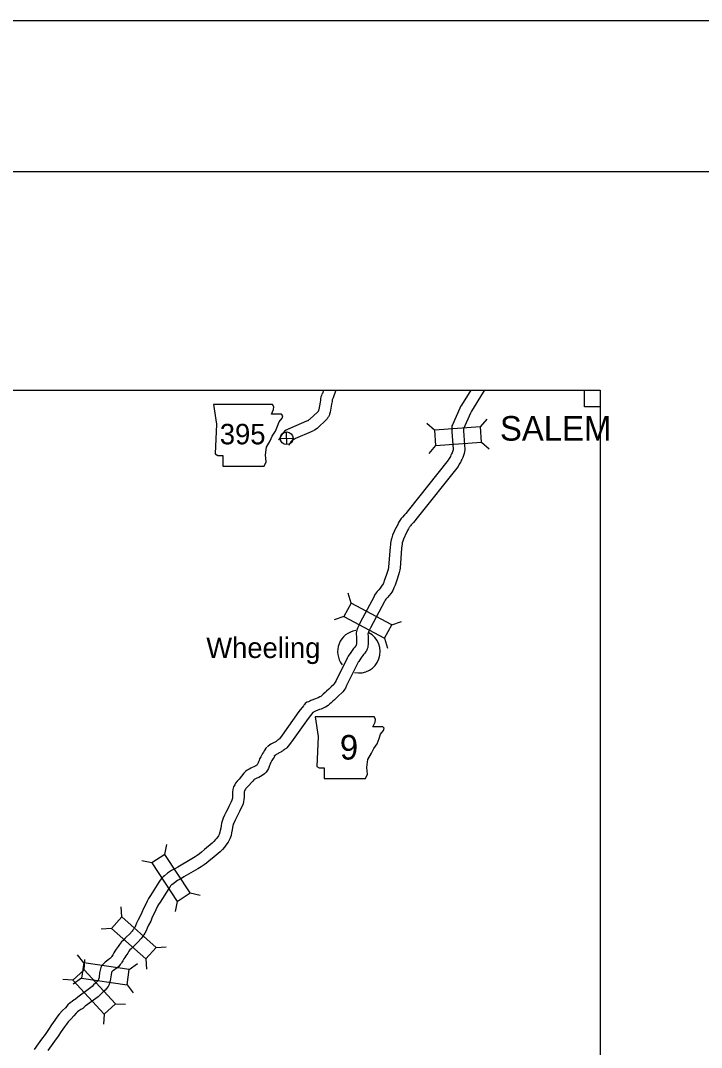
# Model space of a CAD drawing. Extents: x 1377389 to 1380723, y 1168351 to 1170484.
# Drawn here: x 1378129.6 to 1378305.3, y 1170219.2 to 1170484.1 of the extents above; entities that cross this region are included whole.
import ezdxf

# ---------------------------------------------------------------- set-up
doc = ezdxf.new("R2010")
doc.units = 0
doc.layers.add('B_Fill', color=7, linetype='Continuous')
doc.layers.add('B_Text', color=7, linetype='Continuous')

msp = doc.modelspace()

# ---------------------------------------------------------------- linework, layer by layer
msp.add_line((1377513.42, 1170445.16), (1380675.22, 1170445.16))
at = {"layer": 'B_Fill'}
for p, q in [((1378275.14, 1170384.45), (1378275.07, 1170388.77)), ((1378275.07, 1170388.77), (1378279.16, 1170388.77)), ((1378279.16, 1170388.77), (1378279.16, 1170384.42)), ((1378279.16, 1170384.42), (1378275.14, 1170384.45)), ((1378236.4, 1170378.4), (1378234.4, 1170380.12)), ((1378248.25, 1170379.3), (1378249.97, 1170381.3)), ((1378198.32, 1170374.72), (1378198.24, 1170377.98)), ((1378196.65, 1170376.31), (1378199.91, 1170376.39)), ((1378236.7, 1170374.45), (1378234.98, 1170372.45)), ((1378248.55, 1170375.35), (1378250.55, 1170373.63)), ((1378214.89, 1170333.82), (1378214.12, 1170336.35)), ((1378213.04, 1170330.33), (1378210.51, 1170329.55)), ((1378225.39, 1170328.26), (1378227.91, 1170329.04)), ((1378223.54, 1170324.76), (1378224.31, 1170322.24)), ((1378166.84, 1170268.99), (1378167.38, 1170271.57)), ((1378163.53, 1170266.82), (1378160.95, 1170267.35)), ((1378173.36, 1170259.05), (1378175.94, 1170258.51)), ((1378155.72, 1170252.87), (1378155.56, 1170255.51)), ((1378170.04, 1170256.88), (1378169.51, 1170254.3)), ((1378153.09, 1170249.91), (1378150.45, 1170249.75)), ((1378164.6, 1170244.98), (1378167.23, 1170245.14)), ((1378145.91, 1170240.99), (1378144.33, 1170243.11)), ((1378146.08, 1170239.26), (1378146.2, 1170241.89)), ((1378161.97, 1170242.02), (1378162.12, 1170239.38)), ((1378157.67, 1170239.29), (1378159.78, 1170240.87)), ((1378143.15, 1170236.59), (1378140.51, 1170236.71)), ((1378145.34, 1170237.08), (1378143.23, 1170235.49)), ((1378157.1, 1170235.37), (1378158.68, 1170233.26)), ((1378154.09, 1170230.48), (1378156.72, 1170230.36)), ((1378151.16, 1170227.81), (1378151.04, 1170225.17))]:
    msp.add_line(p, q, dxfattribs=at)
for points in [[(1378207.79, 1170388.77), (1378207.48, 1170387.93), (1378207.36, 1170387.68), (1378207.23, 1170387.37), (1378207.1, 1170387.02), (1378207.03, 1170386.55), (1378206.99, 1170386.17), (1378206.92, 1170385.65), (1378206.59, 1170383.78), (1378206.52, 1170383.56), (1378206.48, 1170383.45), (1378206.46, 1170383.43), (1378206.43, 1170383.37), (1378206.36, 1170383.28), (1378206.12, 1170383), (1378204.36, 1170381.38), (1378204.16, 1170381.17), (1378204.03, 1170381.08), (1378203.72, 1170380.87)], [(1378210.98, 1170388.77), (1378210.26, 1170386.79), (1378210.1, 1170386.45), (1378210.02, 1170386.27), (1378210, 1170386.17), (1378209.97, 1170385.83), (1378209.88, 1170385.18), (1378209.51, 1170383.06), (1378209.34, 1170382.53), (1378209.29, 1170382.4), (1378209.23, 1170382.22), (1378209.04, 1170381.88), (1378208.9, 1170381.67), (1378208.69, 1170381.38), (1378208.27, 1170380.9), (1378206.48, 1170379.25), (1378206.11, 1170378.86), (1378205.71, 1170378.59), (1378205.41, 1170378.39)], [(1378245.75, 1170388.77), (1378243.37, 1170384.89), (1378243.15, 1170384.51), (1378242.96, 1170384.08), (1378241.01, 1170379.83), (1378240.92, 1170379.57), (1378240.89, 1170379.37), (1378240.84, 1170379.11), (1378240.84, 1170378.62), (1378240.86, 1170378.49), (1378240.85, 1170378.34), (1378240.88, 1170378.02), (1378241.22, 1170373.54), (1378241.2, 1170373.35), (1378241.15, 1170373.11), (1378241.07, 1170372.82), (1378241, 1170372.62), (1378240.83, 1170372.3), (1378240.64, 1170371.95), (1378240.51, 1170371.67), (1378240.34, 1170371.37), (1378240.2, 1170371.12), (1378240.05, 1170370.85), (1378239.93, 1170370.66), (1378229.59, 1170357.71), (1378228.98, 1170356.93), (1378228.7, 1170356.6), (1378228.15, 1170356), (1378227.85, 1170355.63), (1378227.65, 1170355.38), (1378227.46, 1170355.1), (1378227.3, 1170354.85), (1378227.06, 1170354.42), (1378226.91, 1170354.14), (1378226.76, 1170353.87), (1378226.48, 1170353.28)], [(1378249.33, 1170388.77), (1378249.14, 1170388.52), (1378248.96, 1170388.26), (1378245.95, 1170383.35), (1378245.83, 1170383.15), (1378245.7, 1170382.85), (1378243.85, 1170378.82), (1378243.88, 1170378.66), (1378243.86, 1170378.4), (1378243.87, 1170378.27), (1378244.24, 1170373.46), (1378244.16, 1170372.87), (1378244.08, 1170372.44), (1378243.93, 1170371.9), (1378243.74, 1170371.4), (1378243.49, 1170370.9), (1378243.31, 1170370.57), (1378243.17, 1170370.29), (1378242.96, 1170369.91), (1378242.81, 1170369.65), (1378242.48, 1170369.05), (1378231.94, 1170355.85), (1378231.31, 1170355.05), (1378230.96, 1170354.62), (1378230.41, 1170354.03), (1378230.2, 1170353.77), (1378230.07, 1170353.61), (1378229.95, 1170353.43), (1378229.87, 1170353.3), (1378229.69, 1170352.98), (1378229.56, 1170352.74), (1378229.45, 1170352.52), (1378229.18, 1170351.98)], [(1378203.89, 1170380.97), (1378203.64, 1170380.84), (1378203.36, 1170380.72), (1378199.3, 1170378.98), (1378198.94, 1170378.8), (1378198.83, 1170378.75), (1378198.48, 1170378.62), (1378198.14, 1170378.42), (1378197.75, 1170378.15), (1378197.57, 1170377.94), (1378197.43, 1170377.81), (1378197.24, 1170377.58), (1378196.73, 1170376.92), (1378196.18, 1170375.84)], [(1378205.25, 1170378.3), (1378204.93, 1170378.14), (1378204.57, 1170377.97), (1378200.56, 1170376.26), (1378200.26, 1170376.1), (1378199.99, 1170375.98), (1378199.78, 1170375.9), (1378199.62, 1170375.75), (1378199.57, 1170375.69), (1378199.27, 1170375.3), (1378198.86, 1170374.49)], [(1378226.47, 1170353.26), (1378225.59, 1170351.36), (1378225.39, 1170350.68), (1378225.21, 1170350.15), (1378225.11, 1170349.7), (1378225.04, 1170349.29), (1378225.03, 1170348.88), (1378224.94, 1170348.3), (1378224.52, 1170343.1), (1378224.5, 1170342.81), (1378224.48, 1170342.7), (1378224.42, 1170342.49), (1378224.04, 1170341.22), (1378223.46, 1170339.58), (1378223.3, 1170339.23), (1378223.15, 1170338.82), (1378223.06, 1170338.56), (1378222.95, 1170338.42), (1378222.77, 1170338.16), (1378222.37, 1170337.68), (1378222.02, 1170337.25), (1378221.59, 1170336.83), (1378221.38, 1170336.49), (1378220.91, 1170335.86), (1378220.87, 1170335.62), (1378220.83, 1170335.55), (1378217.27, 1170328.83), (1378216.86, 1170328.08), (1378216.7, 1170327.72), (1378216.54, 1170327.32), (1378216.47, 1170327.08), (1378216.39, 1170326.84), (1378216.3, 1170326.51), (1378216.24, 1170326.15), (1378216.22, 1170325.77), (1378216.26, 1170325.16), (1378216.28, 1170323.39), (1378216.25, 1170323.21), (1378216.22, 1170323.03), (1378216.22, 1170323.01), (1378216.21, 1170323), (1378216.17, 1170322.93), (1378216.02, 1170322.71), (1378215.82, 1170322.47), (1378215.55, 1170322.14), (1378214.98, 1170321.36), (1378214.63, 1170320.86), (1378214.34, 1170320.4), (1378214.14, 1170320.1), (1378213.88, 1170319.58), (1378211.04, 1170313.86), (1378210.81, 1170313.4), (1378210.64, 1170313.13), (1378210.49, 1170312.88), (1378210.44, 1170312.81), (1378210.44, 1170312.81), (1378209.73, 1170312.21), (1378209.16, 1170311.63), (1378208.58, 1170311.1), (1378208.19, 1170310.75), (1378207.7, 1170310.32), (1378207.38, 1170309.99), (1378207.15, 1170309.79), (1378207.07, 1170309.74), (1378206.86, 1170309.68), (1378206.37, 1170309.4), (1378206.16, 1170309.32), (1378205.68, 1170309.16), (1378204.53, 1170308.67), (1378204.25, 1170308.54), (1378203.87, 1170308.39), (1378203.51, 1170308.23), (1378203.08, 1170307.92), (1378202.85, 1170307.67), (1378202.71, 1170307.52), (1378202.59, 1170307.35), (1378201.43, 1170305.83), (1378197.09, 1170299.78)], [(1378229.19, 1170352), (1378228.41, 1170350.31), (1378228.26, 1170349.78), (1378228.1, 1170349.34), (1378228.05, 1170349.12), (1378228.03, 1170348.99), (1378228.02, 1170348.61), (1378227.92, 1170347.96), (1378227.51, 1170342.84), (1378227.47, 1170342.42), (1378227.41, 1170342.07), (1378227.31, 1170341.69), (1378226.9, 1170340.29), (1378226.25, 1170338.47), (1378226.08, 1170338.08), (1378225.96, 1170337.79), (1378225.86, 1170337.51), (1378225.7, 1170337.09), (1378225.38, 1170336.65), (1378225.15, 1170336.33), (1378224.69, 1170335.78), (1378224.25, 1170335.23), (1378223.95, 1170334.94), (1378223.86, 1170334.8), (1378223.67, 1170334.55), (1378223.52, 1170334.22), (1378219.91, 1170327.41), (1378219.55, 1170326.74), (1378219.46, 1170326.55), (1378219.38, 1170326.35), (1378219.33, 1170326.18), (1378219.26, 1170325.95), (1378219.23, 1170325.86), (1378219.23, 1170325.84), (1378219.22, 1170325.79), (1378219.26, 1170325.28), (1378219.28, 1170323.2), (1378219.22, 1170322.72), (1378219.19, 1170322.56), (1378219.17, 1170322.4), (1378219.08, 1170322.05), (1378218.97, 1170321.81), (1378218.83, 1170321.52), (1378218.68, 1170321.3), (1378218.43, 1170320.92), (1378218.13, 1170320.55), (1378217.92, 1170320.3), (1378217.42, 1170319.62), (1378217.13, 1170319.21), (1378216.86, 1170318.77), (1378216.74, 1170318.6), (1378216.57, 1170318.24), (1378213.72, 1170312.53), (1378213.42, 1170311.92), (1378213.19, 1170311.55), (1378213, 1170311.24), (1378212.79, 1170310.94), (1378212.52, 1170310.65), (1378211.77, 1170310.01), (1378211.25, 1170309.48), (1378210.59, 1170308.87), (1378210.18, 1170308.51), (1378209.77, 1170308.14), (1378209.44, 1170307.81), (1378208.97, 1170307.4), (1378208.33, 1170306.98), (1378208.03, 1170306.89), (1378207.67, 1170306.69), (1378207.19, 1170306.5), (1378206.74, 1170306.35), (1378205.73, 1170305.92), (1378205.41, 1170305.77), (1378205.06, 1170305.64), (1378205.03, 1170305.59), (1378203.84, 1170304.04), (1378199.53, 1170298.04)], [(1378197.09, 1170299.79), (1378196.39, 1170298.81), (1378196.31, 1170298.73), (1378196.28, 1170298.71), (1378196.12, 1170298.59), (1378195.95, 1170298.44), (1378195.84, 1170298.36), (1378195.7, 1170298.26), (1378195.53, 1170298.14), (1378195.4, 1170298.06), (1378195.28, 1170297.99), (1378195.05, 1170297.87), (1378194.7, 1170297.7), (1378194.52, 1170297.58), (1378194.39, 1170297.52), (1378194.18, 1170297.41), (1378193.48, 1170296.94), (1378193.38, 1170296.83), (1378193.26, 1170296.75)], [(1378199.52, 1170298.03), (1378198.7, 1170296.89), (1378198.36, 1170296.53), (1378198.15, 1170296.36), (1378198, 1170296.25), (1378197.84, 1170296.12), (1378197.63, 1170295.95), (1378197.4, 1170295.78), (1378197.18, 1170295.64), (1378196.98, 1170295.51), (1378196.74, 1170295.37), (1378196.38, 1170295.18), (1378196.2, 1170295.09), (1378196.01, 1170294.96), (1378195.72, 1170294.83), (1378195.62, 1170294.77), (1378195.45, 1170294.65), (1378195.29, 1170294.51), (1378195, 1170294.31)], [(1378193.15, 1170296.67), (1378192.93, 1170296.44), (1378192.66, 1170295.99), (1378192.5, 1170295.71), (1378192.27, 1170295.36), (1378192.05, 1170295.02), (1378191.88, 1170294.71), (1378191.58, 1170294.2), (1378191.3, 1170293.67), (1378191.14, 1170293.21), (1378191.05, 1170292.91), (1378190.93, 1170292.6), (1378190.87, 1170292.47), (1378190.77, 1170292.29), (1378190.65, 1170292.11), (1378190.54, 1170291.99), (1378190.34, 1170291.85), (1378190.12, 1170291.72), (1378189.82, 1170291.58), (1378189.39, 1170291.39), (1378189.01, 1170291.23), (1378188.57, 1170291.03), (1378188.1, 1170290.77), (1378187.67, 1170290.37), (1378187.26, 1170289.92), (1378185.98, 1170288.42), (1378185.49, 1170287.92), (1378185.11, 1170287.41), (1378184.87, 1170286.97), (1378184.57, 1170286.4), (1378184.39, 1170285.72), (1378184.32, 1170285.09), (1378184.3, 1170284.68), (1378184.3, 1170284.21), (1378184.3, 1170283.89), (1378184.28, 1170283.54), (1378184.23, 1170283.29), (1378184.15, 1170282.95), (1378184, 1170282.53), (1378183.73, 1170282.06), (1378183.38, 1170281.32), (1378183.03, 1170280.58), (1378182.61, 1170279.79), (1378182.26, 1170279.13), (1378181.91, 1170278.35), (1378181.68, 1170277.85), (1378181.46, 1170277.08), (1378181.34, 1170276.37), (1378181.27, 1170275.81), (1378181.15, 1170275.19), (1378181.04, 1170274.72), (1378180.86, 1170274.17), (1378180.66, 1170273.77), (1378180.23, 1170273.2), (1378179.95, 1170272.84), (1378179.48, 1170272.32), (1378179.07, 1170271.88), (1378177.09, 1170270.27), (1378176.34, 1170269.61), (1378175.76, 1170269.15), (1378175.22, 1170268.74), (1378174.65, 1170268.35), (1378173.85, 1170267.9), (1378170.19, 1170265.73), (1378169.63, 1170265.38), (1378169.22, 1170265.16), (1378168.57, 1170264.81), (1378167.53, 1170264.13), (1378166.76, 1170263.5), (1378166.43, 1170263.23), (1378166.02, 1170262.81), (1378165.67, 1170262.34), (1378165.33, 1170261.85), (1378163.15, 1170258.37), (1378162.65, 1170257.65), (1378162.29, 1170256.96), (1378161.82, 1170256.01), (1378161.36, 1170255.05), (1378160.88, 1170254.01), (1378160.48, 1170253.1), (1378159.98, 1170252.12), (1378159.56, 1170251.23), (1378159.28, 1170250.58), (1378159.08, 1170250.17), (1378158.95, 1170249.96), (1378158.86, 1170249.84), (1378158.71, 1170249.63), (1378158.58, 1170249.43), (1378158.4, 1170249.2), (1378157.72, 1170248.44), (1378156.96, 1170247.7), (1378156.53, 1170247.29), (1378156.08, 1170246.83), (1378155.64, 1170246.41), (1378155.14, 1170245.77), (1378154.77, 1170245.22), (1378154.3, 1170244.52), (1378153.97, 1170244.04), (1378153.7, 1170243.58), (1378153.43, 1170243.09), (1378153.15, 1170242.66)], [(1378195.34, 1170294.62), (1378195.24, 1170294.46), (1378195.04, 1170294.12), (1378194.79, 1170293.74), (1378194.62, 1170293.48), (1378194.47, 1170293.21), (1378194.2, 1170292.74), (1378194.06, 1170292.49), (1378193.99, 1170292.28), (1378193.88, 1170291.93), (1378193.7, 1170291.45), (1378193.55, 1170291.12), (1378193.31, 1170290.69), (1378192.99, 1170290.23), (1378192.56, 1170289.76), (1378191.97, 1170289.32), (1378191.5, 1170289.06), (1378191.07, 1170288.85), (1378190.56, 1170288.63), (1378190.22, 1170288.49), (1378189.93, 1170288.35), (1378189.88, 1170288.32), (1378189.8, 1170288.25), (1378189.51, 1170287.93), (1378188.19, 1170286.39), (1378187.77, 1170285.96), (1378187.65, 1170285.79), (1378187.52, 1170285.56), (1378187.38, 1170285.3), (1378187.35, 1170285.18), (1378187.32, 1170284.84), (1378187.3, 1170284.59), (1378187.3, 1170284.21), (1378187.3, 1170283.8), (1378187.26, 1170283.19), (1378187.17, 1170282.65), (1378187.02, 1170282.08), (1378186.74, 1170281.27), (1378186.4, 1170280.68), (1378186.1, 1170280.04), (1378185.71, 1170279.22), (1378185.26, 1170278.38), (1378184.96, 1170277.81), (1378184.63, 1170277.1), (1378184.5, 1170276.82), (1378184.39, 1170276.41), (1378184.31, 1170275.94), (1378184.24, 1170275.35), (1378184.08, 1170274.56), (1378183.94, 1170273.92), (1378183.64, 1170273.02), (1378183.21, 1170272.18), (1378182.61, 1170271.38), (1378182.24, 1170270.9), (1378181.68, 1170270.29), (1378181.12, 1170269.69), (1378179.03, 1170267.98), (1378178.26, 1170267.31), (1378177.59, 1170266.77), (1378176.97, 1170266.31), (1378176.24, 1170265.8), (1378175.35, 1170265.3), (1378171.76, 1170263.18), (1378171.14, 1170262.78), (1378170.63, 1170262.51), (1378170.11, 1170262.23), (1378169.3, 1170261.71), (1378168.65, 1170261.17), (1378168.47, 1170261.03), (1378168.31, 1170260.86), (1378168.11, 1170260.59), (1378167.85, 1170260.21), (1378165.65, 1170256.71), (1378165.22, 1170256.09), (1378164.97, 1170255.61), (1378164.52, 1170254.7), (1378164.07, 1170253.77), (1378163.61, 1170252.78), (1378163.2, 1170251.82), (1378162.67, 1170250.79), (1378162.3, 1170250.01), (1378162.01, 1170249.31), (1378161.7, 1170248.72), (1378161.44, 1170248.28), (1378161.29, 1170248.08), (1378161.18, 1170247.92), (1378160.99, 1170247.65), (1378160.7, 1170247.28), (1378159.89, 1170246.37), (1378159.05, 1170245.54), (1378158.64, 1170245.15), (1378158.18, 1170244.68), (1378157.86, 1170244.38), (1378157.57, 1170244.01), (1378157.27, 1170243.55), (1378156.77, 1170242.82), (1378156.51, 1170242.44), (1378156.31, 1170242.1), (1378156, 1170241.55), (1378155.7, 1170241.06)], [(1378153.21, 1170242.74), (1378152.99, 1170242.44), (1378152.83, 1170242.25), (1378152.58, 1170242.04), (1378152.17, 1170241.73), (1378151.76, 1170241.43), (1378151.45, 1170241.17), (1378151.07, 1170240.84), (1378150.59, 1170240.36), (1378150.36, 1170239.86), (1378150.24, 1170239.5), (1378150.15, 1170239.13), (1378150.02, 1170238.43), (1378149.87, 1170237.39), (1378149.8, 1170237.03), (1378149.73, 1170236.75), (1378149.68, 1170236.6), (1378149.62, 1170236.47), (1378149.57, 1170236.4), (1378149.34, 1170236.17), (1378148.93, 1170235.79), (1378148.47, 1170235.36), (1378148.06, 1170234.93), (1378147.73, 1170234.63), (1378144.41, 1170232.2), (1378143.83, 1170231.67), (1378143.48, 1170231.45), (1378142.93, 1170231.06), (1378142.44, 1170230.69), (1378141.86, 1170230.16), (1378141.2, 1170229.45), (1378140.48, 1170228.7), (1378139.6, 1170227.78), (1378139.03, 1170227.04), (1378138.49, 1170226.27), (1378137.61, 1170225.01), (1378136.81, 1170223.81), (1378135.94, 1170222.57), (1378135.07, 1170221.38), (1378134.21, 1170220.13), (1378133.13, 1170218.64)], [(1378155.64, 1170240.98), (1378155.34, 1170240.56), (1378154.94, 1170240.11), (1378154.45, 1170239.69), (1378153.96, 1170239.33), (1378153.62, 1170239.08), (1378153.39, 1170238.88), (1378153.12, 1170238.65), (1378153.12, 1170238.65), (1378153.09, 1170238.51), (1378152.99, 1170237.95), (1378152.83, 1170236.87), (1378152.73, 1170236.37), (1378152.61, 1170235.9), (1378152.46, 1170235.47), (1378152.2, 1170234.91), (1378151.84, 1170234.44), (1378151.43, 1170234.02), (1378150.97, 1170233.59), (1378150.59, 1170233.24), (1378150.16, 1170232.79), (1378149.63, 1170232.3), (1378146.31, 1170229.87), (1378145.66, 1170229.28), (1378145.16, 1170228.97), (1378144.7, 1170228.63), (1378144.34, 1170228.37), (1378143.97, 1170228.03), (1378143.39, 1170227.4), (1378142.65, 1170226.62), (1378141.88, 1170225.82), (1378141.44, 1170225.25), (1378140.94, 1170224.55), (1378140.09, 1170223.32), (1378139.29, 1170222.12), (1378138.37, 1170220.81), (1378137.51, 1170219.64), (1378136.66, 1170218.4)]]:
    msp.add_lwpolyline(points, dxfattribs=at)
for points in [[(1378179.43, 1170385.08), (1378180.19, 1170380), (1378179.85, 1170372.31), (1378180.53, 1170371.88), (1378181.8, 1170371.88), (1378181.8, 1170369.18), (1378192.46, 1170369.18), (1378192.96, 1170370.28), (1378192.79, 1170372.05), (1378193.05, 1170374.08), (1378193.98, 1170375.69), (1378194.57, 1170376.88), (1378195.42, 1170378.14), (1378195.92, 1170379.5), (1378196.35, 1170380.6), (1378197.11, 1170381.53), (1378197.28, 1170382.12), (1378196.94, 1170382.54), (1378194.32, 1170382.54), (1378194.91, 1170383.73), (1378194.99, 1170384.49), (1378194.64, 1170385.07)], [(1378236.7, 1170374.45), (1378248.55, 1170375.35), (1378248.25, 1170379.3), (1378236.4, 1170378.4)], [(1378225.39, 1170328.26), (1378214.89, 1170333.82), (1378213.04, 1170330.33), (1378223.54, 1170324.76)], [(1378205.6, 1170304.49), (1378206.36, 1170299.41), (1378206.03, 1170291.71), (1378206.7, 1170291.29), (1378207.97, 1170291.29), (1378207.97, 1170288.58), (1378218.63, 1170288.58), (1378219.14, 1170289.68), (1378218.97, 1170291.46), (1378219.22, 1170293.49), (1378220.15, 1170295.1), (1378220.74, 1170296.28), (1378221.59, 1170297.55), (1378222.1, 1170298.9), (1378222.52, 1170300), (1378223.28, 1170300.93), (1378223.45, 1170301.53), (1378223.11, 1170301.95), (1378220.49, 1170301.95), (1378221.08, 1170303.13), (1378221.17, 1170303.89), (1378220.82, 1170304.48)], [(1378173.36, 1170259.05), (1378166.84, 1170268.99), (1378163.53, 1170266.82), (1378170.04, 1170256.88)], [(1378164.6, 1170244.98), (1378155.72, 1170252.87), (1378153.09, 1170249.91), (1378161.97, 1170242.02)], [(1378143.15, 1170236.59), (1378151.16, 1170227.81), (1378154.09, 1170230.48), (1378146.08, 1170239.26)], [(1378145.34, 1170237.08), (1378157.1, 1170235.37), (1378157.67, 1170239.29), (1378145.91, 1170240.99)]]:
    msp.add_lwpolyline(points, close=True, dxfattribs=at)
msp.add_circle((1378198.28, 1170376.35), 1.63, dxfattribs=at)
for start, end in [(98.6526, 217.8749), (258.4398, 61.7827)]:
    msp.add_arc((1378216.91, 1170321.31), 5.5, start, end, dxfattribs=at)
at = {"layer": 'B_Text'}
msp.add_line((1377389.41, 1170484.1), (1380722.75, 1170484.1), dxfattribs=at)
for points in [[(1377389.35, 1170484.1), (1380722.75, 1170484.1), (1380722.75, 1168350.73), (1377389.35, 1168350.73)], [(1377549.76, 1170388.77), (1378279.16, 1170388.77), (1378279.16, 1169604.28), (1377549.76, 1169604.28)]]:
    msp.add_lwpolyline(points, close=True, dxfattribs=at)

# ---------------------------------------------------------------- texts
at = {"layer": 'B_Fill'}
for s, height, p in [('395', 5.28, (1378181.03, 1170374.78)), ('SALEM', 6.336, (1378253.29, 1170375.74)), ('Wheeling', 5.28, (1378177.54, 1170319.66)), ('9', 6.34, (1378212, 1170293.47))]:
    msp.add_text(s, height=height, dxfattribs=at).set_placement(p)

doc.saveas('drawing.dxf')
